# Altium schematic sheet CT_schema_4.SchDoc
size 362 x 192 mm
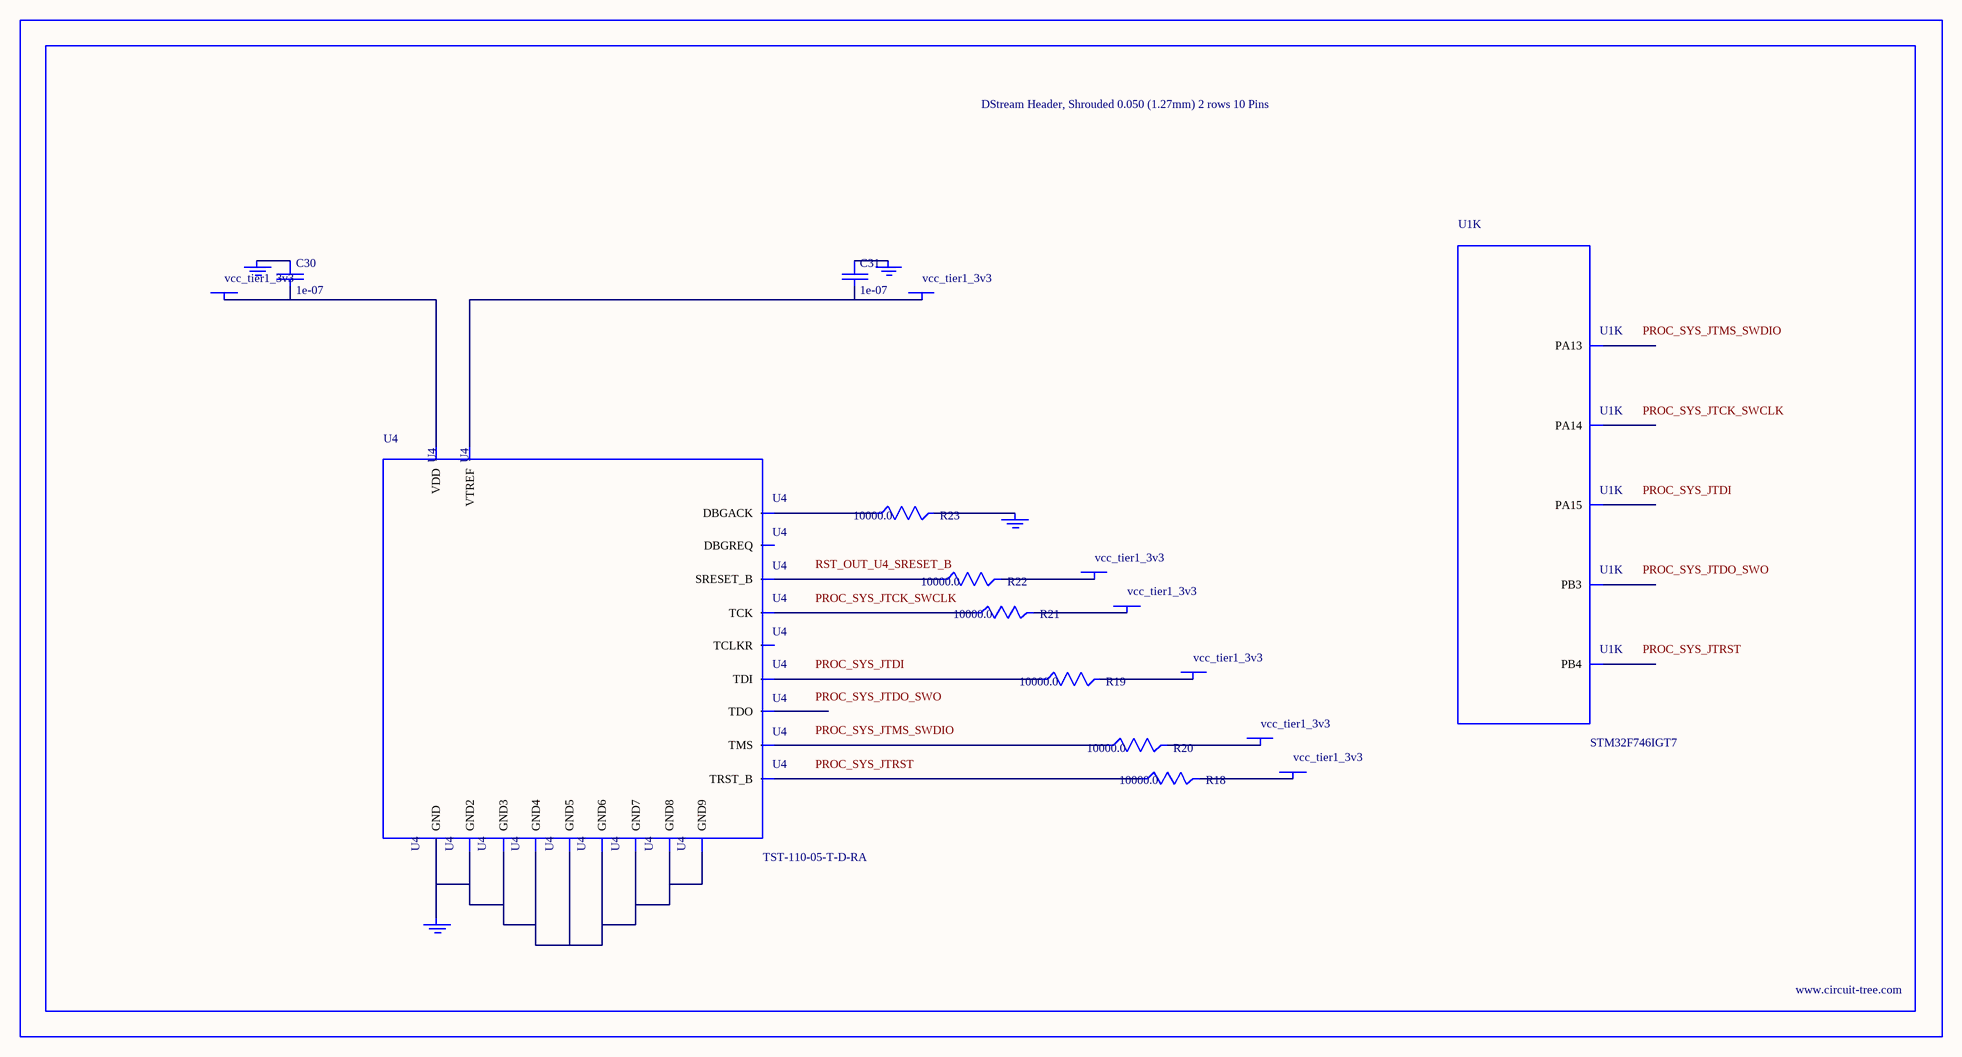
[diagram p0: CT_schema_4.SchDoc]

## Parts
BORDER3  (no value)
C30  1e-07  [C0402]
C31  1e-07  [C0402]
GND_INSTANCE_3_0  (no value)
GND_INSTANCE_3_1  (no value)
GND_INSTANCE_3_2  (no value)
GND_INSTANCE_3_3  (no value)
POWER_INSTANCE_3_0  vcc_tier1_3v3
POWER_INSTANCE_3_1  vcc_tier1_3v3
POWER_INSTANCE_3_2  vcc_tier1_3v3
POWER_INSTANCE_3_3  vcc_tier1_3v3
POWER_INSTANCE_3_4  vcc_tier1_3v3
POWER_INSTANCE_3_5  vcc_tier1_3v3
POWER_INSTANCE_3_6  vcc_tier1_3v3
R18  10000.0  [R0603]
R19  10000.0  [R0603]
R20  10000.0  [R0603]
R21  10000.0  [R0603]
R22  10000.0  [R0603]
R23  10000.0  [R0603]
U1  STM32F746IGT7  [LQFP176]  (part K of 15)
U4  TST-110-05-T-D-RA  [TST-110-05-T-D-RA]

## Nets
NetC30_1: C30.1 GND_INSTANCE_3_1.0(GND)
NetC30_2: C30.2 POWER_INSTANCE_3_1.0(PWR) U4.2(VDD)
NetC31_1: C31.1 GND_INSTANCE_3_0.0(GND)
NetC31_2: C31.2 POWER_INSTANCE_3_0.0(PWR) U4.1(VTREF)
NetGND_INSTANCE_3_2_0: GND_INSTANCE_3_2.0(GND) R23.2
NetGND_INSTANCE_3_3_0: GND_INSTANCE_3_3.0(GND) U4.4(GND) U4.6(GND2) U4.8(GND3) U4.10(GND4) U4.12(GND5) U4.14(GND6) U4.16(GND7) U4.18(GND8) U4.20(GND9)
NetPOWER_INSTANCE_3_2_0: POWER_INSTANCE_3_2.0(PWR) R18.2
NetPOWER_INSTANCE_3_3_0: POWER_INSTANCE_3_3.0(PWR) R19.2
NetPOWER_INSTANCE_3_4_0: POWER_INSTANCE_3_4.0(PWR) R20.2
NetPOWER_INSTANCE_3_5_0: POWER_INSTANCE_3_5.0(PWR) R21.2
NetPOWER_INSTANCE_3_6_0: POWER_INSTANCE_3_6.0(PWR) R22.2
NetR18_1: R18.1 U4.3(TRST_B)
NetR19_1: R19.1 U4.5(TDI)
NetR20_1: R20.1 U4.7(TMS)
NetR21_1: R21.1 U4.9(TCK)
NetR22_1: R22.1 U4.15(SRESET_B)
NetR23_1: R23.1 U4.19(DBGACK)

Not connected (* = marked no-connect by the designer): U1 124(PA13) 137(PA14) 138(PA15) 161(PB3) 162(PB4); U4 11(TCLKR) 13(TDO) 17(DBGREQ)

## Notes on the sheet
- Labels drawn without touching a wire or pin: PROC_SYS_JTCK_SWCLK, PROC_SYS_JTDI, PROC_SYS_JTDO_SWO, PROC_SYS_JTMS_SWDIO, PROC_SYS_JTRST, RST_OUT_U4_SRESET_B

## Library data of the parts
BORDER3 = BORDER_PAGE3
C30 C31 = C0402C104K3RACTU
GND_INSTANCE_3_0-GND_INSTANCE_3_3 = GND
POWER_INSTANCE_3_0-POWER_INSTANCE_3_6 = PWR
R18-R23 = RC0603JR-0710KL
